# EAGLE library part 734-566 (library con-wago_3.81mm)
Serie 734, Federleiste mit abgewinkelten Einlötstiften / Series 734, Female connector with angled solder pins Polzahl / Pole No.: 6 Bemessungsspannung / Rated Voltage: 160 V Nennstrom / Nominal Current: 10 A Lötstiftlänge: / Solder Pin Length: 3.8 mm Farbe / Color: orange / orange Stand: 01.01.2012. Die jeweils aktuellen Daten zu diesem Artikel finden Sie in unserem Produktkatalog, den Sie unter www.wago.com einsehen können. As of: 01/01/2012. Please find the newest data for this article in our product catalogue, which can be viewed under www.wago.com.
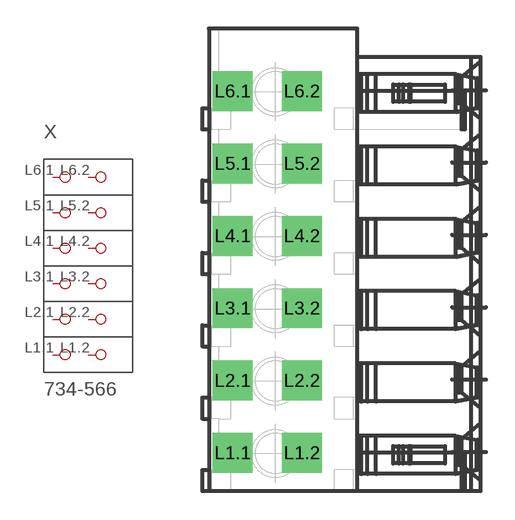
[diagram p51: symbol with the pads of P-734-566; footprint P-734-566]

Designator prefix X

## 734-566  [P-734-566]
L1.1  P1.1
L1.2  P1.2
L2.1  P2.1
L2.2  P2.2
L3.1  P3.1
L3.2  P3.2
L4.1  P4.1
L4.2  P4.2
L5.1  P5.1
L5.2  P5.2
L6.1  P6.1
L6.2  P6.2

## Footprint P-734-566 (pad centres in mm)
drill 1.4 square: L1.1 -5.875,-10.17; L1.2 -2.225,-10.17; L2.1 -5.875,-6.36; L2.2 -2.225,-6.36; L3.1 -5.875,-2.55; L3.2 -2.225,-2.55; L4.1 -5.875,1.26; L4.2 -2.225,1.26; L5.1 -5.875,5.07; L5.2 -2.225,5.07; L6.1 -5.875,8.88; L6.2 -2.225,8.88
